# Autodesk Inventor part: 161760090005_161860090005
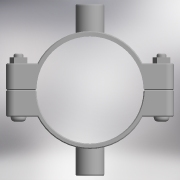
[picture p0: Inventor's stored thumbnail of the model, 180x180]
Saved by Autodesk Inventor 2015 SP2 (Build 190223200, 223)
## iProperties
Created: 2017-05
Part Number: 161760090005_161860090005
Material: Generic
Description: PLASSON DOUBLE SADDLE 90-1/2"
Document SubType Name: Modeling
Designer: KIM
Density: 1 g/cm^3
Appearance: Default
Author: KIM
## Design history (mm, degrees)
derived "16176.ipt"
feature "Solid1::16176.ipt"
feature "Solid2::16176.ipt"
tag "TaggingFeature1"
body "Solid1"
body "Solid2"
other parameters: "d0" = 99, "d1" = 141, "d2" = 45, "d4" = 105, "d5" = 0, "d6" = 7.05, "d7" = 141, "d8" = 0.1, "d10" = 0, "d11" = 0.9, "d20" = 0.9, "d23" = 0.9, "d36" = 13, "d37" = 10.4, "d38" = 53, "d39" = 0, "d40" = 3, "d41" = 5, "d42" = 0, "d43" = 8, "d44" = 3, "d45" = 0, "d46" = 0.9, "d52" = 18.631, "d53" = 18, "d54" = 0, "d55" = 16, "d57" = 0, "d58" = 97.2, "d60" = 0, "d62" = 13, "d63" = 10.4, "d66" = 84.2, "d67" = 144, "d68" = 24.2203, "d69" = 18.631, "d70" = 18, "d71" = 0, "d72" = 16, "d74" = 0, "d75" = 0.9, "B_" = 16, "G_" = 18.631, "A_" = 72, "L_" = 141, "L_1" = 105, "l_2" = 18
